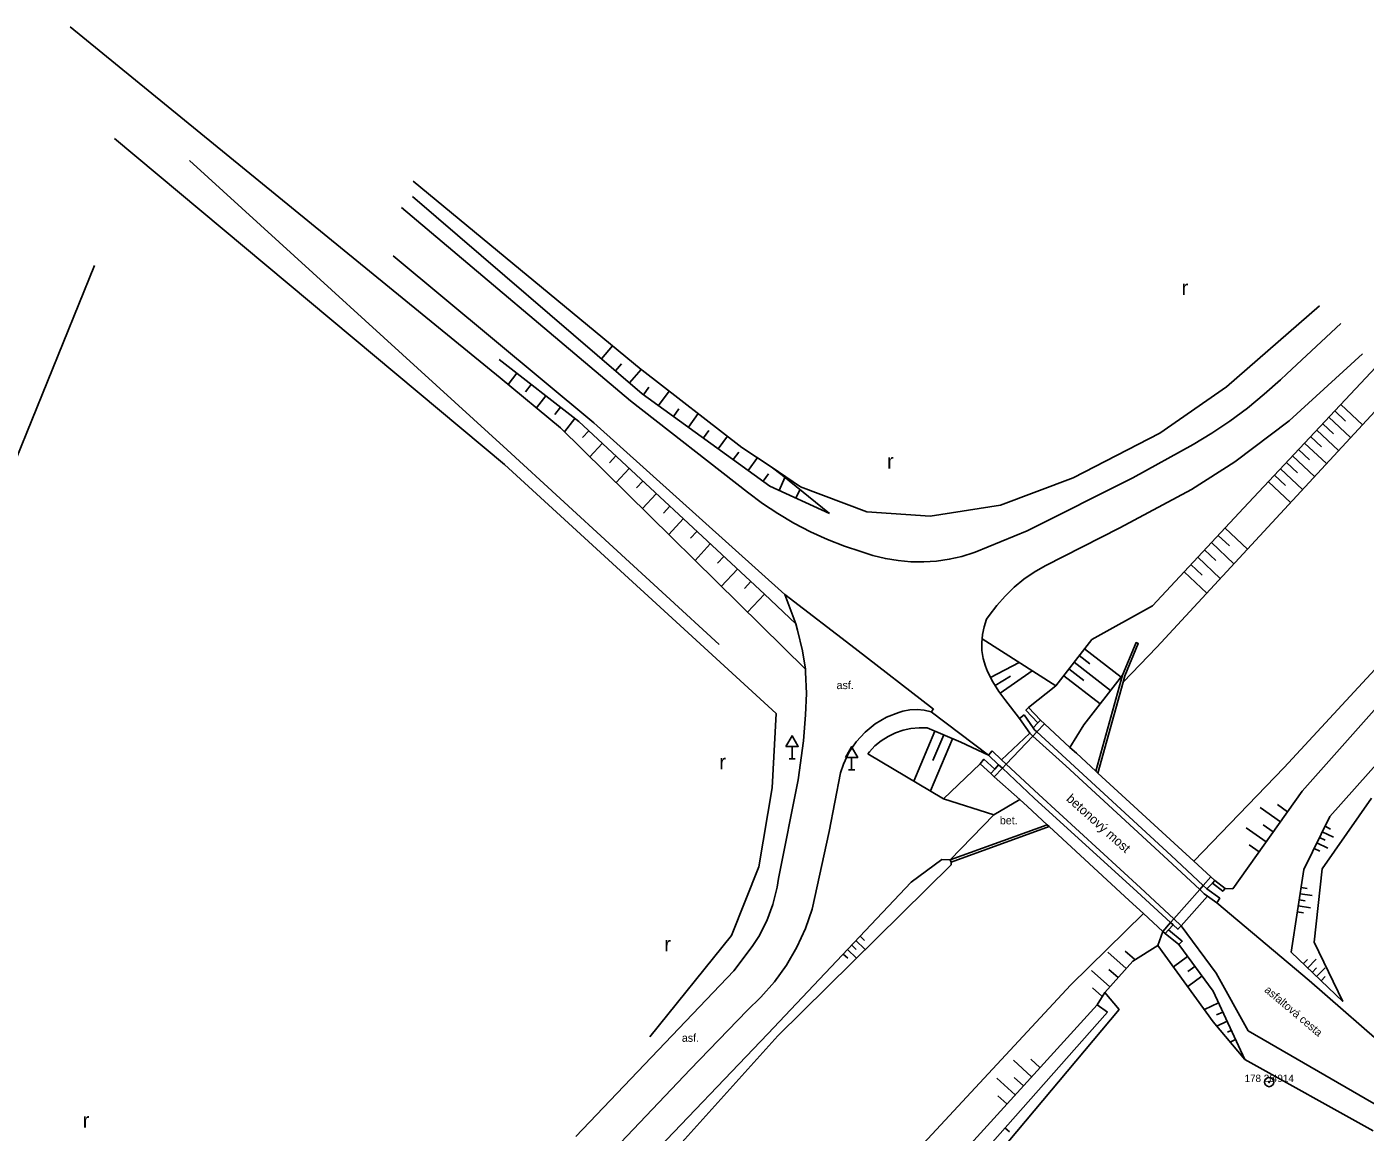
# Model space of a CAD drawing. Extents: x -538441 to -536770, y -1181008 to -1179809.
# Drawn here: x -537761.3 to -537652.5, y -1180026.4 to -1179936.6 of the extents above; entities that cross this region are included whole.
import ezdxf

# ---------------------------------------------------------------- set-up
doc = ezdxf.new("R2010")
doc.units = 0
for name, color, linetype in [('Vrstva 10', 7, 'Continuous'), ('Vrstva 11', 7, 'Continuous'), ('Vrstva 14', 7, 'Continuous'), ('Vrstva 15', 7, 'Continuous'), ('Vrstva 21', 7, 'Continuous'), ('Vrstva 22', 7, 'Continuous'), ('Vrstva 23', 7, 'Continuous'), ('Vrstva 34', 7, 'Continuous'), ('Vrstva 36', 7, 'Continuous'), ('Vrstva 40', 7, 'Continuous'), ('Vrstva 41', 7, 'Continuous'), ('Vrstva 7', 7, 'Continuous')]:
    doc.layers.add(name, color=color, linetype=linetype)

msp = doc.modelspace()

# ---------------------------------------------------------------- linework, layer by layer
at = {"layer": 'Vrstva 10'}
for p, q in [((-537698.816, -1179985.093), (-537699.712, -1179982.697)), ((-537699.712, -1179982.697), (-537693.985, -1179987.075)), ((-537693.985, -1179987.075), (-537687.618, -1179992.019)), ((-537687.618, -1179992.019), (-537687.812, -1179992.24)), ((-537700.213, -1180005.792), (-537698.63, -1179997.751)), ((-537695.173, -1179997.208), (-537696.089, -1180001.963)), ((-537696.089, -1180001.963), (-537697.472, -1180008.276)), ((-537716.687, -1180026.743), (-537703.855, -1180013.301)), ((-537702.764, -1180016.503), (-537707.386, -1180021.299)), ((-537707.386, -1180021.299), (-537721.188, -1180035.809))]:
    msp.add_line(p, q, dxfattribs=at)
for points in [[(-537698.01, -1179992.489), (-537697.935, -1179990.75), (-537698.02, -1179989.011), (-537698.032, -1179988.768), (-537698.264, -1179987.287), (-537698.665, -1179985.593), (-537698.816, -1179985.093)], [(-537690.446, -1179992.293), (-537691.434, -1179992.682), (-537692.351, -1179993.216), (-537693.179, -1179993.881), (-537693.897, -1179994.662), (-537694.49, -1179995.543), (-537694.944, -1179996.502), (-537695.173, -1179997.208)], [(-537687.812, -1179992.24), (-537688.376, -1179992.108), (-537688.952, -1179992.055), (-537689.531, -1179992.081), (-537690.1, -1179992.187), (-537690.446, -1179992.293)], [(-537698.63, -1179997.751), (-537698.178, -1179994.588), (-537698.01, -1179992.489)], [(-537701.823, -1180010.508), (-537701.176, -1180009.228), (-537700.675, -1180007.884), (-537700.327, -1180006.493), (-537700.213, -1180005.792)], [(-537697.472, -1180008.276), (-537698.024, -1180009.855), (-537698.723, -1180011.374), (-537699.565, -1180012.819), (-537700.541, -1180014.178), (-537701.642, -1180015.436), (-537702.764, -1180016.503)], [(-537703.855, -1180013.301), (-537702.357, -1180011.322), (-537701.823, -1180010.508)]]:
    msp.add_lwpolyline(points, dxfattribs=at)
at = {"layer": 'Vrstva 11'}
for p, q in [((-537730.86, -1179951.25), (-537712.26, -1179966.95)), ((-537731.53, -1179955.18), (-537715.22, -1179968.75)), ((-537658.889, -1179964.761), (-537654.504, -1179960.665)), ((-537652.754, -1179963.138), (-537658.708, -1179968.591)), ((-537712.26, -1179966.95), (-537702.733, -1179974.39)), ((-537715.22, -1179968.75), (-537699.712, -1179982.697)), ((-537658.708, -1179968.591), (-537663.132, -1179971.928)), ((-537671.42, -1179973.207), (-537666.506, -1179970.508)), ((-537663.132, -1179971.928), (-537666.651, -1179974.152)), ((-537680.004, -1179977.518), (-537671.42, -1179973.207)), ((-537666.651, -1179974.152), (-537672.462, -1179977.288)), ((-537684.226, -1179979.259), (-537680.004, -1179977.518)), ((-537672.462, -1179977.288), (-537678.537, -1179980.359)), ((-537694.84, -1179978.771), (-537693.536, -1179979.208)), ((-537680.623, -1179992.766), (-537681.813, -1179991.228)), ((-537683.154, -1179995.755), (-537687.812, -1179992.24)), ((-537680.252, -1179992.471), (-537680.623, -1179992.766)), ((-537679.21, -1179993.864), (-537679.403, -1179993.686)), ((-537668.299, -1180003.913), (-537679.21, -1179993.864)), ((-537682.86, -1179995.407), (-537683.154, -1179995.755)), ((-537683.829, -1179996.466), (-537686.811, -1179999.296)), ((-537682.635, -1179996.888), (-537682.326, -1179996.531)), ((-537668.567, -1180004.258), (-537676.86, -1179996.624)), ((-537674.25, -1179997.213), (-537667.722, -1180003.223)), ((-537680.603, -1179999.371), (-537682.7, -1180000.61)), ((-537679.422, -1179999.252), (-537671.071, -1180006.872)), ((-537679.06, -1179998.957), (-537670.778, -1180006.554)), ((-537686.26, -1180004.28), (-537682.7, -1180000.61)), ((-537678.213, -1180001.565), (-537671.72, -1180007.566)), ((-537664.733, -1180005.958), (-537663.914, -1180006.586)), ((-537667.494, -1180009.632), (-537665.337, -1180007.228)), ((-537664.596, -1180007.759), (-537657.064, -1180014.079)), ((-537667.494, -1180009.632), (-537664.63, -1180013.479)), ((-537668.982, -1180010.079), (-537669.369, -1180011.217)), ((-537668.792, -1180010.253), (-537667.68, -1180011.16)), ((-537664.63, -1180013.479), (-537662.049, -1180018.161)), ((-537657.064, -1180014.079), (-537649.871, -1180020.384)), ((-537662.049, -1180018.161), (-537651.294, -1180024.366))]:
    msp.add_line(p, q, dxfattribs=at)
for points in [[(-537666.506, -1179970.508), (-537664.992, -1179969.586), (-537663.522, -1179968.596), (-537662.097, -1179967.541), (-537660.722, -1179966.423), (-537659.398, -1179965.244), (-537658.889, -1179964.761)], [(-537702.733, -1179974.39), (-537701.52, -1179975.291), (-537700.262, -1179976.127), (-537698.961, -1179976.894), (-537697.621, -1179977.592), (-537696.246, -1179978.218), (-537694.84, -1179978.771)], [(-537693.536, -1179979.208), (-537692.543, -1179979.532), (-537691.529, -1179979.779), (-537690.499, -1179979.948), (-537689.458, -1179980.038), (-537688.414, -1179980.047), (-537687.373, -1179979.977), (-537686.339, -1179979.827), (-537685.321, -1179979.599), (-537684.322, -1179979.293), (-537684.226, -1179979.259)], [(-537678.537, -1179980.359), (-537679.421, -1179980.878), (-537680.261, -1179981.465), (-537681.053, -1179982.115), (-537681.792, -1179982.825), (-537682.473, -1179983.591), (-537683.093, -1179984.407), (-537683.294, -1179984.703)], [(-537683.294, -1179984.703), (-537683.507, -1179985.318), (-537683.642, -1179985.955), (-537683.672, -1179986.301), (-537683.699, -1179986.604), (-537683.676, -1179987.254), (-537683.573, -1179987.897), (-537683.392, -1179988.522), (-537683.217, -1179988.952)], [(-537683.217, -1179988.952), (-537682.79, -1179989.785), (-537682.294, -1179990.579), (-537681.813, -1179991.228)], [(-537678.924, -1179992.912), (-537679.904, -1179991.89), (-537677.663, -1179990.125)], [(-537679.904, -1179991.89), (-537680.101, -1179992.104), (-537679.121, -1179993.126)], [(-537682.671, -1179997.511), (-537682.016, -1179996.821), (-537681.702, -1179996.49), (-537679.531, -1179994.202), (-537679.21, -1179993.864), (-537678.594, -1179993.215)], [(-537682.088, -1179996.129), (-537679.774, -1179993.981), (-537680.623, -1179992.766)], [(-537679.403, -1179993.686), (-537679.504, -1179993.542), (-537680.252, -1179992.471)], [(-537678.924, -1179992.912), (-537679.121, -1179993.126), (-537679.504, -1179993.542)], [(-537678.924, -1179992.912), (-537678.594, -1179993.215), (-537676.52, -1179995.124), (-537675.999, -1179995.603)], [(-537676.86, -1179996.624), (-537679.531, -1179994.202), (-537679.774, -1179993.981)], [(-537682.86, -1179995.407), (-537682.088, -1179996.129), (-537681.702, -1179996.49), (-537679.06, -1179998.957)], [(-537675.999, -1179995.603), (-537674.415, -1179997.061), (-537674.25, -1179997.213)], [(-537682.635, -1179996.888), (-537683.513, -1179996.095), (-537683.829, -1179996.466)], [(-537683.829, -1179996.466), (-537682.951, -1179997.259), (-537682.635, -1179996.888)], [(-537683.154, -1179995.755), (-537682.326, -1179996.531), (-537682.016, -1179996.821), (-537679.422, -1179999.252)], [(-537682.951, -1179997.259), (-537682.671, -1179997.511), (-537680.603, -1179999.371), (-537679.977, -1179999.935)], [(-537679.977, -1179999.935), (-537678.378, -1180001.413), (-537678.213, -1180001.565)], [(-537667.722, -1180003.223), (-537666.45, -1180004.387), (-537665.061, -1180005.658), (-537664.733, -1180005.958)], [(-537668.567, -1180004.258), (-537665.976, -1180006.689), (-537665.613, -1180007.03)], [(-537668.299, -1180003.913), (-537665.687, -1180006.364), (-537665.396, -1180006.633)], [(-537665.061, -1180005.658), (-537665.687, -1180006.364), (-537665.976, -1180006.689), (-537668.09, -1180009.073), (-537668.344, -1180009.36), (-537668.982, -1180010.079)], [(-537664.733, -1180005.958), (-537664.945, -1180006.174), (-537665.396, -1180006.633)], [(-537663.914, -1180006.586), (-537664.097, -1180006.824), (-537664.945, -1180006.174)], [(-537671.72, -1180007.566), (-537670.547, -1180008.642), (-537668.982, -1180010.079), (-537668.792, -1180010.253)], [(-537671.071, -1180006.872), (-537668.344, -1180009.36), (-537668.142, -1180009.544)], [(-537670.778, -1180006.554), (-537668.09, -1180009.073), (-537667.494, -1180009.632)], [(-537665.613, -1180007.03), (-537665.337, -1180007.228), (-537664.596, -1180007.759)], [(-537665.396, -1180006.633), (-537664.344, -1180007.387), (-537664.596, -1180007.759)], [(-537668.792, -1180010.253), (-537668.525, -1180009.962), (-537668.142, -1180009.544)], [(-537668.142, -1180009.544), (-537667.753, -1180009.908), (-537667.494, -1180009.632)], [(-537668.525, -1180009.962), (-537667.39, -1180010.888), (-537667.68, -1180011.16)]]:
    msp.add_lwpolyline(points, dxfattribs=at)
at = {"layer": 'Vrstva 14'}
for p, q in [((-537722.84, -1179965.09), (-537757.8, -1179936.55)), ((-537711.389, -1179964.396), (-537729.91, -1179949.1)), ((-537711.3, -1179966.38), (-537729.98, -1179950.34)), ((-537646.603, -1179962.245), (-537669.474, -1179986.989)), ((-537716.46, -1179968.64), (-537722.91, -1179963.6)), ((-537717.94, -1179969.15), (-537722.84, -1179965.09)), ((-537711.302, -1179964.464), (-537711.389, -1179964.396)), ((-537703.196, -1179970.752), (-537711.302, -1179964.464)), ((-537662.413, -1179975.691), (-537651.66, -1179964.212)), ((-537700.91, -1179973.89), (-537711.3, -1179966.38)), ((-537698.032, -1179988.768), (-537717.94, -1179969.15)), ((-537701.364, -1179982.675), (-537716.46, -1179968.64)), ((-537700.82, -1179972.334), (-537703.196, -1179970.752)), ((-537636.16, -1179971.94), (-537659.11, -1179996.77)), ((-537657.65, -1179998.68), (-537634.58, -1179972.69)), ((-537696.08, -1179976.12), (-537700.91, -1179973.89)), ((-537655.4, -1180000.75), (-537631.94, -1179974.3)), ((-537669.816, -1179983.609), (-537662.413, -1179975.691)), ((-537698.816, -1179985.093), (-537701.364, -1179982.675)), ((-537674.757, -1179986.354), (-537669.816, -1179983.609)), ((-537683.672, -1179986.301), (-537677.663, -1179990.125)), ((-537677.663, -1179990.125), (-537674.757, -1179986.354)), ((-537669.474, -1179986.989), (-537672.2, -1179989.818)), ((-537672.25, -1179989.25), (-537675.39, -1179993.28)), ((-537675.39, -1179993.28), (-537676.52, -1179995.124)), ((-537692.954, -1179995.646), (-537686.811, -1179999.296)), ((-537659.11, -1179996.77), (-537666.45, -1180004.387)), ((-537663.27, -1180006.63), (-537657.65, -1179998.68)), ((-537686.811, -1179999.296), (-537682.7, -1180000.61)), ((-537656.03, -1180005.01), (-537652, -1179999.25)), ((-537657.51, -1180005.05), (-537655.4, -1180000.75)), ((-537700.26, -1180018.56), (-537686.19, -1180004.67)), ((-537686.19, -1180004.67), (-537686.192, -1180004.468)), ((-537658.55, -1180011.78), (-537657.51, -1180005.05)), ((-537656.68, -1180010.95), (-537656.03, -1180005.01)), ((-537701.07, -1180018.42), (-537689.43, -1180006.07)), ((-537663.914, -1180006.586), (-537663.27, -1180006.63)), ((-537670.547, -1180008.642), (-537676.46, -1180014.42)), ((-537664.874, -1180017.439), (-537669.369, -1180011.217)), ((-537667.68, -1180011.16), (-537664.89, -1180014.951)), ((-537654.35, -1180015.79), (-537658.55, -1180011.78)), ((-537654.35, -1180015.79), (-537656.68, -1180010.95)), ((-537676.46, -1180014.42), (-537692.8, -1180032.01)), ((-537672.51, -1180016.44), (-537673.69, -1180015.06)), ((-537664.89, -1180014.951), (-537662.302, -1180020.495)), ((-537674.31, -1180016.04), (-537690, -1180033.28)), ((-537673.47, -1180016.64), (-537674.31, -1180016.04)), ((-537689.34, -1180034.56), (-537673.47, -1180016.64)), ((-537688.47, -1180035.4), (-537672.51, -1180016.44)), ((-537727.775, -1180046.287), (-537701.07, -1180018.42)), ((-537662.302, -1180020.495), (-537664.874, -1180017.439)), ((-537726.397, -1180047.533), (-537700.26, -1180018.56)), ((-537662.302, -1180020.495), (-537651.865, -1180026.3))]:
    msp.add_line(p, q, dxfattribs=at)
for points in [[(-537696.08, -1179976.12), (-537699.92, -1179973.01), (-537700.82, -1179972.334)], [(-537688.126, -1179993.549), (-537688.787, -1179993.528), (-537689.446, -1179993.587), (-537690.093, -1179993.725), (-537690.718, -1179993.94), (-537691.313, -1179994.229), (-537691.868, -1179994.588), (-537692.377, -1179995.011), (-537692.83, -1179995.492), (-537692.954, -1179995.646)], [(-537683.154, -1179995.755), (-537685.4, -1179994.702), (-537688.126, -1179993.549)], [(-537689.43, -1180006.07), (-537686.93, -1180004.24), (-537686.26, -1180004.28)], [(-537669.369, -1180011.217), (-537671.41, -1180012.49), (-537673.69, -1180015.06), (-537674.31, -1180016.04)]]:
    msp.add_lwpolyline(points, dxfattribs=at)
at = {"layer": 'Vrstva 15'}
for p, q in [((-537714.608, -1179963.54), (-537713.703, -1179962.485)), ((-537713.47, -1179964.517), (-537712.981, -1179963.948)), ((-537721.494, -1179964.707), (-537722.205, -1179965.616)), ((-537712.332, -1179965.494), (-537711.389, -1179964.396)), ((-537720.312, -1179965.63), (-537720.774, -1179966.221)), ((-537711.187, -1179966.462), (-537710.747, -1179965.854)), ((-537709.971, -1179967.341), (-537709.117, -1179966.159)), ((-537719.13, -1179966.554), (-537719.894, -1179967.531)), ((-537654.507, -1179967.251), (-537652.751, -1179968.896)), ((-537717.948, -1179967.477), (-537718.41, -1179968.068)), ((-537716.766, -1179968.401), (-537717.607, -1179969.478)), ((-537708.755, -1179968.219), (-537708.316, -1179967.612)), ((-537707.54, -1179969.098), (-537706.745, -1179967.999)), ((-537655.487, -1179968.297), (-537653.724, -1179969.949)), ((-537654.997, -1179967.774), (-537654.117, -1179968.598)), ((-537715.646, -1179969.397), (-537716.156, -1179969.946)), ((-537706.324, -1179969.977), (-537705.885, -1179969.369)), ((-537656.467, -1179969.344), (-537654.697, -1179971.001)), ((-537655.977, -1179968.82), (-537655.094, -1179969.648)), ((-537714.547, -1179970.418), (-537715.554, -1179971.501)), ((-537705.108, -1179970.856), (-537704.373, -1179969.839)), ((-537657.447, -1179970.39), (-537655.67, -1179972.054)), ((-537656.957, -1179969.867), (-537656.07, -1179970.697)), ((-537713.449, -1179971.44), (-537713.959, -1179971.989)), ((-537703.893, -1179971.734), (-537703.453, -1179971.126)), ((-537702.677, -1179972.613), (-537701.893, -1179971.529)), ((-537658.427, -1179971.436), (-537656.643, -1179973.107)), ((-537657.937, -1179970.913), (-537657.047, -1179971.747)), ((-537712.35, -1179972.461), (-537713.416, -1179973.608)), ((-537659.407, -1179972.482), (-537657.617, -1179974.16)), ((-537658.917, -1179971.959), (-537658.024, -1179972.796)), ((-537711.251, -1179973.482), (-537711.762, -1179974.032)), ((-537701.461, -1179973.492), (-537701.022, -1179972.884)), ((-537700.166, -1179974.234), (-537699.688, -1179973.198)), ((-537660.387, -1179973.529), (-537658.59, -1179975.213)), ((-537659.897, -1179973.005), (-537659, -1179973.846)), ((-537710.153, -1179974.504), (-537711.279, -1179975.715)), ((-537698.804, -1179974.862), (-537698.489, -1179974.182)), ((-537709.054, -1179975.525), (-537709.565, -1179976.074)), ((-537707.956, -1179976.547), (-537709.141, -1179977.821)), ((-537706.857, -1179977.568), (-537707.368, -1179978.117)), ((-537664.469, -1179977.89), (-537663.556, -1179978.744)), ((-537663.914, -1179977.296), (-537662.091, -1179979.001)), ((-537705.759, -1179978.589), (-537707.003, -1179979.928)), ((-537665.58, -1179979.078), (-537664.663, -1179979.935)), ((-537665.024, -1179978.484), (-537663.195, -1179980.195)), ((-537704.66, -1179979.611), (-537705.171, -1179980.16)), ((-537666.69, -1179980.266), (-537665.77, -1179981.126)), ((-537666.135, -1179979.672), (-537664.299, -1179981.389)), ((-537703.562, -1179980.632), (-537704.866, -1179982.035)), ((-537667.246, -1179980.86), (-537665.402, -1179982.583)), ((-537702.463, -1179981.653), (-537702.974, -1179982.203)), ((-537701.364, -1179982.675), (-537702.728, -1179984.141)), ((-537675.765, -1179987.662), (-537674.897, -1179988.331)), ((-537675.344, -1179987.116), (-537672.372, -1179989.406)), ((-537682.973, -1179989.45), (-537680.639, -1179988.232)), ((-537682.19, -1179990.728), (-537679.604, -1179988.89)), ((-537676.607, -1179988.754), (-537675.404, -1179989.681)), ((-537676.186, -1179988.208), (-537673.219, -1179990.494)), ((-537682.603, -1179990.103), (-537681.354, -1179989.337)), ((-537677.027, -1179989.3), (-537674.067, -1179991.582)), ((-537687.497, -1179993.815), (-537689.211, -1179997.87)), ((-537686.07, -1179994.419), (-537687.867, -1179998.668)), ((-537686.783, -1179994.117), (-537687.661, -1179996.193)), ((-537658.837, -1180000.357), (-537659.653, -1179999.78)), ((-537659.414, -1180001.174), (-537661.047, -1180000.02)), ((-537660.568, -1180002.808), (-537662.202, -1180001.653)), ((-537659.991, -1180001.991), (-537660.808, -1180001.414)), ((-537656.009, -1180001.991), (-537655.111, -1180002.432)), ((-537655.789, -1180001.542), (-537655.34, -1180001.762)), ((-537661.145, -1180003.625), (-537661.962, -1180003.047)), ((-537656.449, -1180002.889), (-537655.551, -1180003.329)), ((-537656.229, -1180002.44), (-537655.78, -1180002.66)), ((-537656.669, -1180003.338), (-537656.221, -1180003.558)), ((-537657.891, -1180007.512), (-537657.397, -1180007.589)), ((-537657.814, -1180007.018), (-537656.826, -1180007.17)), ((-537657.739, -1180006.524), (-537657.245, -1180006.6)), ((-537658.043, -1180008.5), (-537657.549, -1180008.577)), ((-537657.968, -1180008.006), (-537656.979, -1180008.158)), ((-537693.921, -1180010.835), (-537693.193, -1180011.521)), ((-537693.578, -1180010.471), (-537693.215, -1180010.814)), ((-537694.95, -1180011.927), (-537694.586, -1180012.27)), ((-537694.607, -1180011.563), (-537693.879, -1180012.248)), ((-537694.264, -1180011.199), (-537693.9, -1180011.542)), ((-537671.943, -1180013.091), (-537673.439, -1180011.764)), ((-537671.28, -1180012.343), (-537672.028, -1180011.679)), ((-537666.964, -1180012.133), (-537668.102, -1180012.971)), ((-537666.381, -1180012.926), (-537666.953, -1180013.347)), ((-537657.562, -1180012.725), (-537657.216, -1180012.363)), ((-537657.199, -1180013.07), (-537656.509, -1180012.346)), ((-537656.477, -1180013.76), (-537655.786, -1180013.037)), ((-537673.271, -1180014.587), (-537674.767, -1180013.26)), ((-537672.607, -1180013.839), (-537673.355, -1180013.175)), ((-537665.797, -1180013.718), (-537666.95, -1180014.566)), ((-537656.838, -1180013.415), (-537656.493, -1180013.054)), ((-537656.114, -1180014.105), (-537655.769, -1180013.744)), ((-537673.934, -1180015.335), (-537674.682, -1180014.671)), ((-537664.446, -1180015.902), (-537665.597, -1180016.439)), ((-537664.1, -1180016.644), (-537664.604, -1180016.879)), ((-537663.753, -1180017.386), (-537664.59, -1180017.777)), ((-537663.407, -1180018.128), (-537663.725, -1180018.277)), ((-537663.06, -1180018.871), (-537663.497, -1180019.075)), ((-537679.638, -1180021.894), (-537681.117, -1180020.548)), ((-537678.965, -1180021.155), (-537679.704, -1180020.482)), ((-537680.984, -1180023.374), (-537682.463, -1180022.027)), ((-537680.311, -1180022.634), (-537681.051, -1180021.961)), ((-537681.657, -1180024.113), (-537682.397, -1180023.44)), ((-537681.808, -1180026.055), (-537681.434, -1180026.387))]:
    msp.add_line(p, q, dxfattribs=at)
at = {"layer": 'Vrstva 21'}
for p, q in [((-537748.09, -1179947.42), (-537722.26, -1179970.95)), ((-537722.26, -1179970.95), (-537705.05, -1179986.75))]:
    msp.add_line(p, q, dxfattribs=at)
for radius in [0.375, 0.05]:
    msp.add_circle((-537660.33, -1180022.33), radius, dxfattribs=at)
at = {"layer": 'Vrstva 23'}
for p, q in [((-537754.2, -1179945.63), (-537722.5, -1179972.13)), ((-537763.47, -1179974.81), (-537755.83, -1179955.95)), ((-537656.236, -1179959.238), (-537663.797, -1179965.822)), ((-537663.797, -1179965.822), (-537669.217, -1179969.573)), ((-537669.217, -1179969.573), (-537676.265, -1179973.227)), ((-537722.5, -1179972.13), (-537700.41, -1179992.362)), ((-537698.416, -1179973.935), (-537700.82, -1179972.334)), ((-537676.265, -1179973.227), (-537682.156, -1179975.441)), ((-537693.03, -1179975.97), (-537698.416, -1179973.935)), ((-537687.889, -1179976.344), (-537693.03, -1179975.97)), ((-537682.156, -1179975.441), (-537687.889, -1179976.344)), ((-537700.41, -1179992.362), (-537700.738, -1179998.41)), ((-537700.738, -1179998.41), (-537701.82, -1180004.83)), ((-537701.82, -1180004.83), (-537704.04, -1180010.405)), ((-537704.04, -1180010.405), (-537710.676, -1180018.643))]:
    msp.add_line(p, q, dxfattribs=at)
at = {"layer": 'Vrstva 34'}
for p, q in [((-537699.112, -1179995.046), (-537699.112, -1179996.064)), ((-537699.362, -1179996.064), (-537698.862, -1179996.064)), ((-537694.273, -1179995.936), (-537694.273, -1179996.954)), ((-537694.523, -1179996.954), (-537694.023, -1179996.954))]:
    msp.add_line(p, q, dxfattribs=at)
for points in [[(-537699.612, -1179995.046), (-537698.612, -1179995.046), (-537699.112, -1179994.18)], [(-537694.773, -1179995.936), (-537693.773, -1179995.936), (-537694.273, -1179995.07)]]:
    msp.add_lwpolyline(points, close=True, dxfattribs=at)
at = {"layer": 'Vrstva 7'}
for p, q in [((-537672.25, -1179989.25), (-537674.415, -1179997.061)), ((-537672.2, -1179989.818), (-537674.25, -1179997.213)), ((-537672.061, -1179989.315), (-537672.2, -1179989.818)), ((-537678.378, -1180001.413), (-537686.26, -1180004.28)), ((-537686.192, -1180004.468), (-537678.213, -1180001.565)), ((-537686.26, -1180004.28), (-537686.192, -1180004.468))]:
    msp.add_line(p, q, dxfattribs=at)
msp.add_lwpolyline([(-537672.061, -1179989.315), (-537670.965, -1179986.687), (-537671.15, -1179986.61), (-537672.25, -1179989.25)], dxfattribs=at)

# ---------------------------------------------------------------- texts
at = {"layer": 'Vrstva 22'}
msp.add_text('178 26 ', height=0.6, dxfattribs=at).set_placement((-537662.33, -1180022.33))
at = {"layer": 'Vrstva 23'}
msp.add_text(' 4914', height=0.6, dxfattribs=at).set_placement((-537660.33, -1180022.33))
at = {"layer": 'Vrstva 36'}
for p in [(-537667.448, -1179958.355), (-537691.39, -1179972.459), (-537705.028, -1179996.902), (-537709.493, -1180011.713), (-537756.771, -1180026.035)]:
    msp.add_text('r', height=1.2, dxfattribs=at).set_placement(p)
at = {"layer": 'Vrstva 40'}
for s, p in [('asf.', (-537695.494, -1179990.388)), ('bet.', (-537682.224, -1180001.379)), ('asf.', (-537708.071, -1180019.059))]:
    msp.add_text(s, height=0.65, dxfattribs=at).set_placement(p)
msp.add_text('asfaltová cesta', height=0.65, rotation=319.81293, dxfattribs=at).set_placement((-537660.766, -1180014.935))
at = {"layer": 'Vrstva 41'}
msp.add_text('betonový most', height=0.75, rotation=318.12608, dxfattribs=at).set_placement((-537676.874, -1179999.395))

doc.saveas('drawing.dxf')
